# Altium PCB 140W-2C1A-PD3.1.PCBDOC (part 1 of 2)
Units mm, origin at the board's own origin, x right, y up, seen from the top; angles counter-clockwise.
Board outline 57.13 x 21.16 mm, 6 copper layers (Top Layer, G02, P03, Mid-Layer 6, Mid-Layer 20, Bottom Layer), stack 1.489 mm thick; 81 components, 79 nets, 331 pads, 164 vias.
Unrouted connection lines stored in the file: 14.
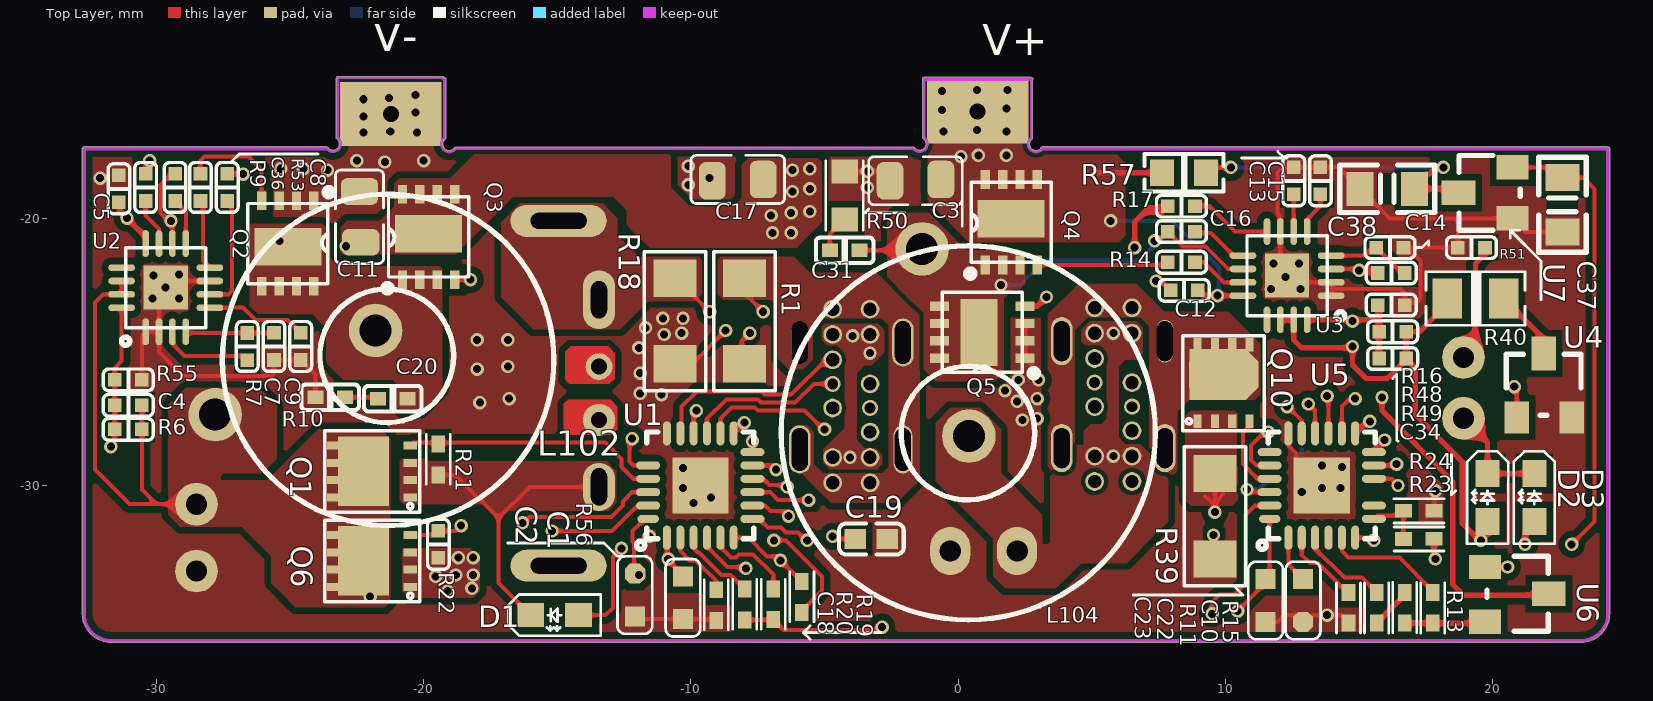
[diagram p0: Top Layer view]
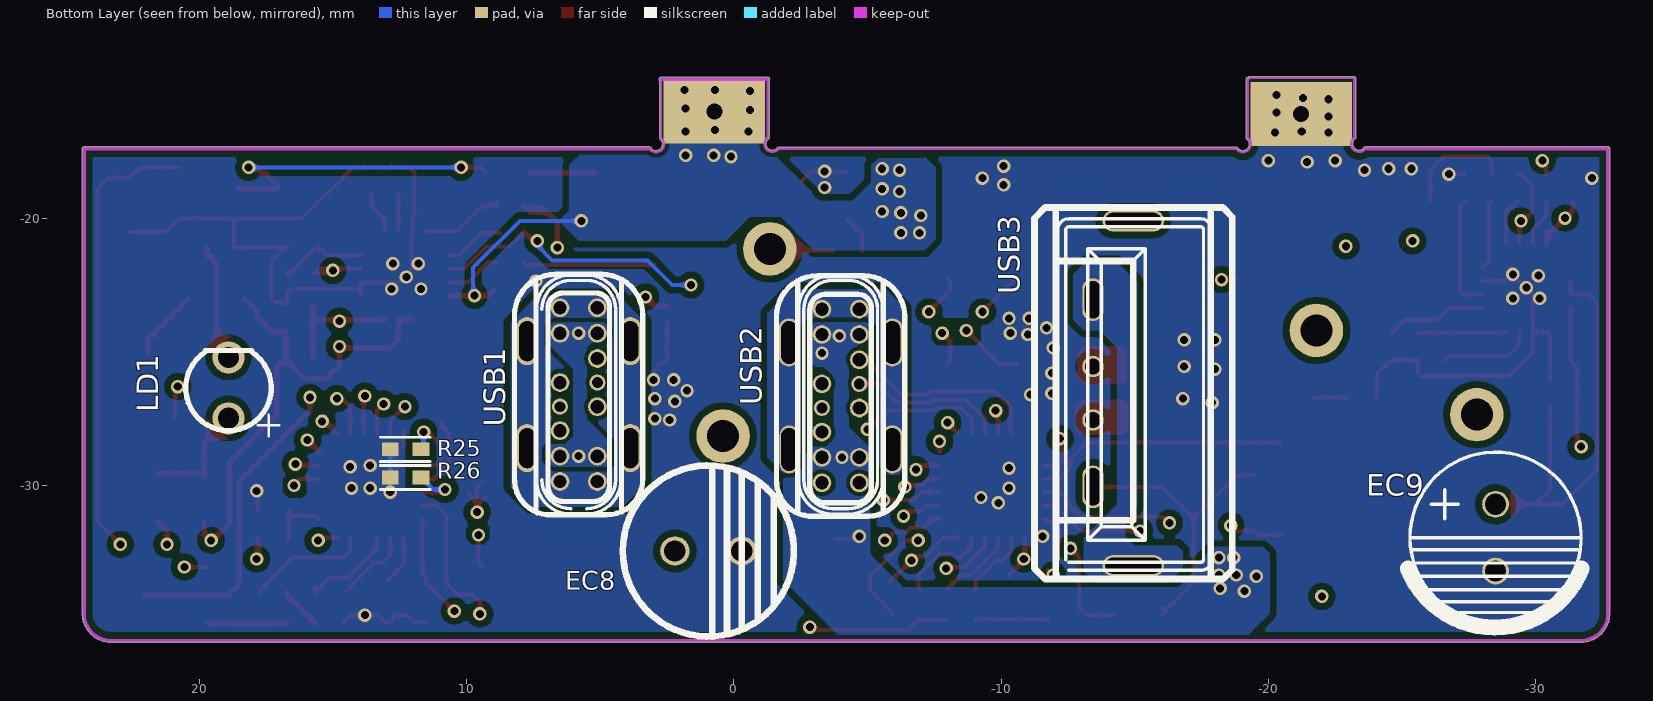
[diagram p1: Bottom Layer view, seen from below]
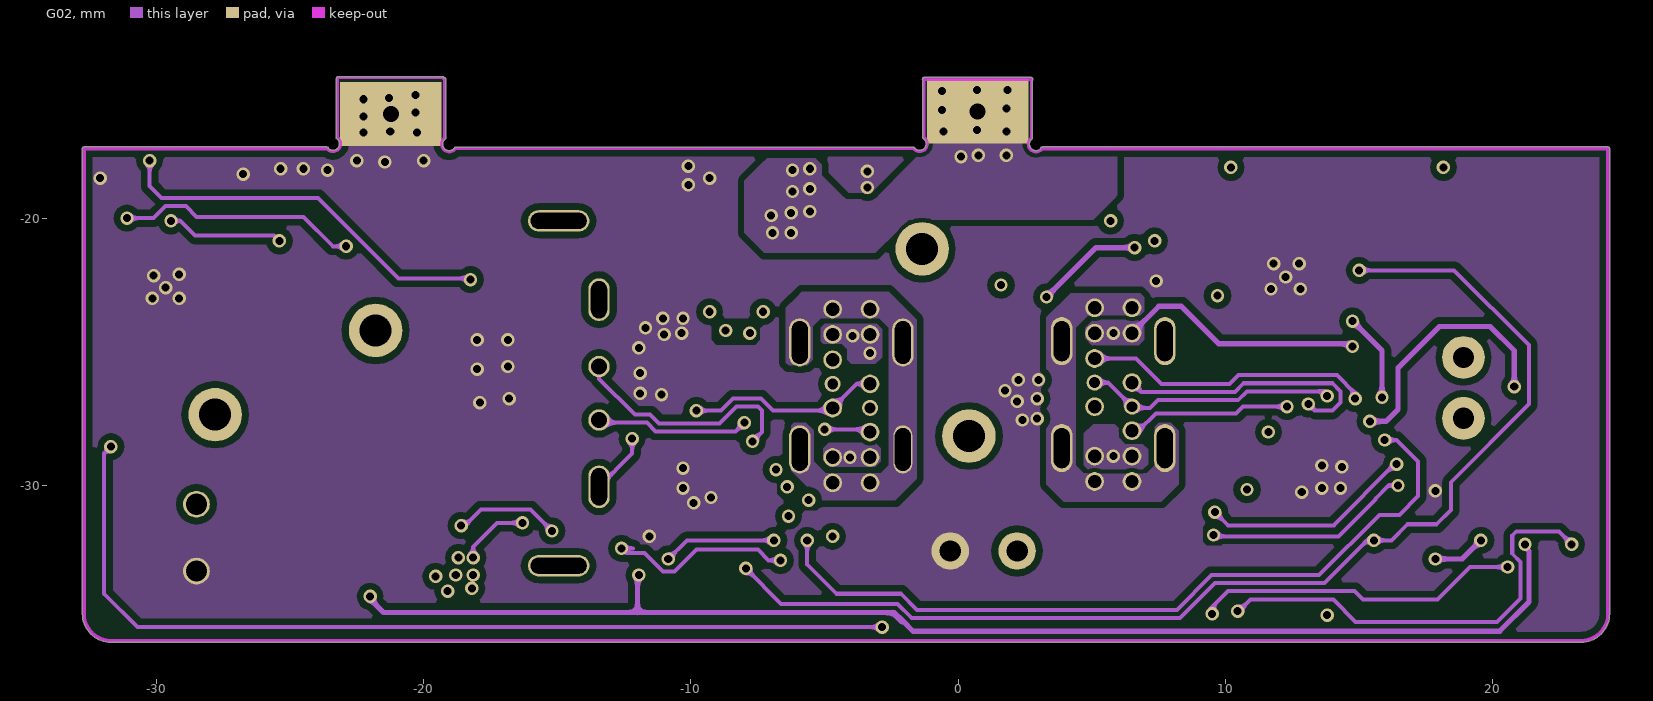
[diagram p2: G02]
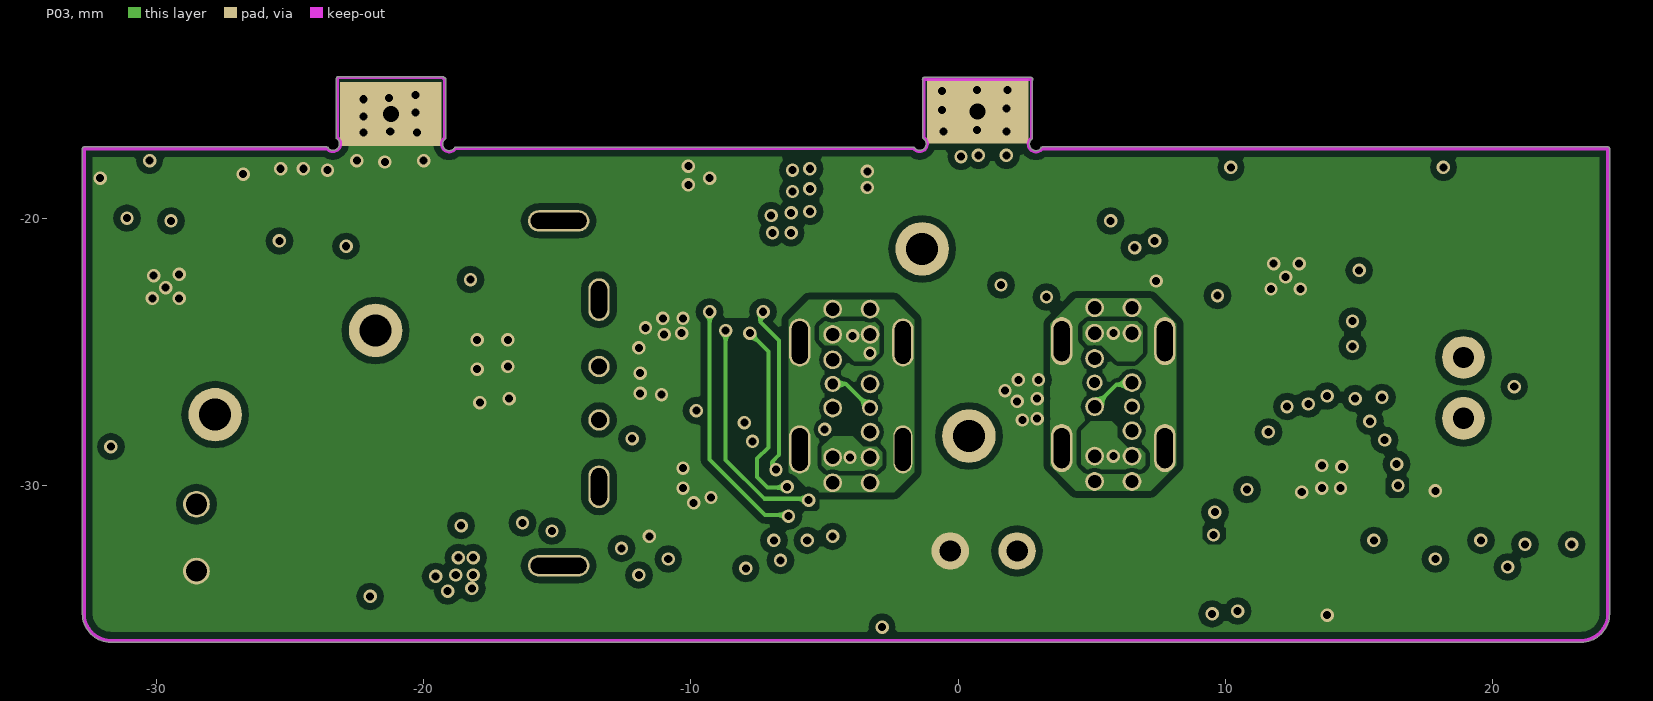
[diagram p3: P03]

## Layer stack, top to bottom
Top Solder: solder mask 0.0102, Solder Resist, Dk 3.5
Top Layer: signal copper 0.0356
Dielectric1: core 0.254, FR-4, Dk 4.2
G02: signal copper 0.036
Dielectric2: prepreg 0.127, Dk 4.2
P03: signal copper 0.036
Dielectric3: core 0.254, Dk 4.2
Mid-Layer 6: signal copper 0.0356
Dielectric4: dielectric 0.32, FR-4, Dk 4.8
Mid-Layer 20: signal copper 0.0356
Dielectric5: dielectric 0.32, FR-4, Dk 4.8
Bottom Layer: signal copper 0.0356
Bottom Solder: solder mask 0.0102, Solder Resist, Dk 3.5

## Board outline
-32.764,-34.8 cw(c-32.7,-34.8) -32.764,-34.799 -32.764,-17.4 cw(c-32.7,-17.4) -32.7,-17.336 -23.625,-17.336 cw(c-23.625,-17.4) -23.561,-17.396 ccw(c-23.393,-17.22) -23.15,-17.22 ccw(c-23.393,-17.22) -23.253,-17.021 cw(c-23.224,-16.98) -23.275,-16.98 -23.275,-14.8 cw(c-23.224,-14.8) -23.25,-14.757 cw(c-23.2,-14.75) -23.2,-14.7 -19.3,-14.7 cw(c-19.3,-14.75) -19.25,-14.75 cw(c-19.3,-14.75) -19.25,-14.756 cw(c-19.225,-14.8) -19.175,-14.8 -19.175,-17 ccw(c-19.225,-17) -19.175,-16.999 -19.175,-17 cw(c-19.225,-17) -19.194,-17.04 ccw(c-19.045,-17.232) -18.846,-17.372 cw(c-18.805,-17.401) -18.805,-17.35 -1.683,-17.35 cw(c-1.675,-17.4) -1.635,-17.369 ccw(c-1.443,-17.22) -1.2,-17.22 ccw(c-1.443,-17.22) -1.303,-17.021 cw(c-1.274,-16.98) -1.325,-16.98 -1.325,-14.839 cw(c-1.274,-14.8) -1.274,-14.736 2.725,-14.736 cw(c2.725,-14.8) 2.789,-14.8 cw(c2.725,-14.8) 2.775,-14.839 2.775,-17 cw(c2.725,-17) 2.756,-17.04 ccw(c2.905,-17.232) 3.081,-17.399 cw(c3.145,-17.4) 3.145,-17.336 24.3,-17.336 cw(c24.3,-17.4) 24.364,-17.4 24.364,-34.8 cw(c24.3,-34.8) 24.364,-34.801 ccw(c23.3,-34.8) 24.364,-34.8 24.364,-34.801 cw(c23.3,-34.8) 23.301,-35.864 cw(c23.3,-35.8) 23.3,-35.864 -31.7,-35.864 cw(c-31.7,-34.8)

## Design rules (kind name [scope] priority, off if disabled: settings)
Clearance Clearance_1 [InNet('NewNet3')] p1: gap=0.254 ignorepadtopadclearanceinfootprint=FALSE except(0: Arc-Hole Track-Hole SMDPad-Hole THPad-Hole Via-Hole Fill-Hole Poly-Hole Region-Hole Text-Hole)
Clearance [All] p2: gap=0.15 ignorepadtopadclearanceinfootprint=FALSE except(0: Arc-Hole Track-Hole SMDPad-Hole THPad-Hole Via-Hole Fill-Hole Poly-Hole Region-Hole Text-Hole)
ComponentClearance [All] p1: gap=0 collisioncheckmode=3 verticalgap=0 showdistances=FALSE
FabricationTestpoint [(IsPad And (OnTopLayer Or OnBottomLayer))] p1: side=3 testpointundercomponent=TRUE minsize=1.016 maxsize=2.54 preferedsize=1.524 minholesize=0 maxholesize=1.016 preferedholesize=0.813 testpointgrid=0.025 allowsidetop=TRUE allowsidebottom=TRUE usegrid=TRUE gridtolerance=0
PolygonConnect [All] p1: connectstyle=Direct reliefconductorwidth=0.254 reliefentries=4 polygonreliefangle="90 Angle" airgapwidth=0.254
RoutingVias [All] p1: holewidth=0.3 width=0.5 viastyle="Through Hole" minholewidth=0.3 minwidth=0.5 maxholewidth=10 maxwidth=10
SilkToSolderMaskClearance SilkscreenOverComponentPads [IsPad] p1: minsilkscreentomaskgap=0.254 clearancetoexposedcopper=TRUE
SolderMaskExpansion [All] p1: expansion=0.102 istentingtop=FALSE
Width [All] p1: maxlimit=10 minlimit=0.15 preferedwidth=0.2
27 further rules are at their usual default settings.

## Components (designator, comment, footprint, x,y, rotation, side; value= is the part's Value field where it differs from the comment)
C1 "2.2uF/25V" 0603C#1 -10.3,-34.2 r270 bottom
C2 "1uF/25V" 0603C#2 -12.1,-34.1 r270 bottom
C3 "25V/10uF" 0805C(W) -1.45,-18.6 r0 top (schematic designator C51)
C4 "50V/220pF" 0402 -31.05,-27 r270 top (schematic designator C39)
C5 "0.1uF" 0402 -31.4,-18.9 r180 top (schematic designator C39)
C7 "2.2uF/10V" 0402 -25.6,-24.8 r0 top (schematic designator C39)
C8 "2.2uF" 0402 -27.35,-18.85 r180 top (schematic designator C49)
C9 "1nF" 0402 -24.6,-24.8 r180 top (schematic designator C35)
C10 "3.3nF" 0402A 15.65,-33.95 r270 top
C11 "25V/10uF" 0805C(W) -22.4,-20.1 r270 top (schematic designator C51)
C12 "0.1uF" 0402 8.45,-22.7 r270 top (schematic designator C39)
C13 "2.2uF/10V" 0402 12.55,-18.6 r180 top (schematic designator C49)
C14 "2.2uF/10V" 0402 16.15,-21.1 r90 top (schematic designator C39)
C15 "1nF" 0402 13.55,-18.6 r0 top (schematic designator C35)
C16 "2.2uF" 0402 8.35,-20.5 r90 top (schematic designator C43)
C17 "10UF/50V  0805" 0805C(W) -8.4,-18.55 r180 top (schematic designator C51)
C18 "15nF" 0402A -7.985,-35.079 r90 top
C19 "1uF/25V" 0603CA -3.25,-32 r180 top
C20 "1nF/50V" CAP-0402 -21.15,-26.75 r180 top (schematic designator C6)
C22 "2.2uF/25V" 0603C#2 12.9,-34.3 r90 bottom
C23 "1uF/25V" 0603C#1 11.5,-34.3 r90 bottom
C31 "1nF/50V" CAP-0402 -4.25,-21.2 r180 top (schematic designator C6)
C34 "50V/220pF" 0402 16.25,-25.25 r90 top (schematic designator C39)
C36 "100nF" 0402 -29.3,-18.85 r0 top (schematic designator C43)
C37 "10uF/25V" CC0805 22.6,-19.5 r90 top
C38 "10UF/35V" CC0805 16.05,-18.9 r180 top
D1 "IN4148" 0603D -15.1,-34.85 r180 bottom
D2 "IN4148  SOD323" 0603D 19.8,-30.45 r90 bottom
D3 "IN4148  SOD323" 0603D 21.55,-30.45 r90 bottom
EC8 "100uF" CE-D6.3-P2.5-PCB -0.3,-32.45 r90 bottom
EC9 "100uF" CE6.3/2.5HA -28.5,-31.95 r180 bottom
L102 "10uH" L13.5*5#1 -21.8,-23.85 r90 top locked
L104 "10uH" L13.5*5#2 0.3,-27.95 r270 top locked
LD1 "Comment" "LED-D3 P2.28" 18.9,-26.35 r270 bottom
Q1 "MOSFET N" DPAK/WAVEAAA#1 -20.5,-28.5 r270 top
Q2 "NMOS" DFN3*3-EPAD -23.6,-19.45 r270 top (schematic designator Q9)
Q3 "NMOS" DFN3*3-EPAD -21.3,-22.2 r90 top (schematic designator Q7)
Q4 "NMOS" DFN3*3-EPAD 0.5,-21.65 r90 top (schematic designator Q7)
Q5 "NMOS" DFN3*3-EPAD 2.4,-25.75 r180 top (schematic designator Q9)
Q6 "MOSFET N" DPAK/WAVEAAA#1 -20.5,-31.85 r270 top
Q10 "MOSFET N" DPAK/WAVEAAA#2 10.9,-27.6 r180 top
R1 "5mR" R1206/WAVE -8,-23.85 r90 top
R6 "100K" 0402 -31.05,-27.9 r90 top (schematic designator R15)
R7 "51K" 0402 -26.6,-24.8 r0 top (schematic designator R15)
R9 "10R" 0402 -30.4,-18.85 r0 top (schematic designator R15)
R10 "2R" CAP-0402 -23.5,-26.7 r180 top (schematic designator R16)
R11 "1K" 0402A 14.6,-33.95 r270 top
R13 "1K   0402" 0402A 17.75,-33.95 r270 top
R14 "10R" 0402 8.35,-21.65 r90 top (schematic designator R15)
R15 "200K" 0402A 16.7,-35.2 r90 top
R16 "51K" 0402 16.2,-22.05 r90 top (schematic designator R15)
R17 "2R" 0402 8.35,-19.55 r270 top (schematic designator R15)
R18 "5mR" R1206/WAVE -10.6,-23.85 r270 top
R19 "100K" 0402A -5.85,-34.8 r90 top
R20 "1K" 0402A -6.919,-35.072 r90 top
R21 "100K" 0402A -19.45,-29.65 r90 top
R22 "100K" 0402 -19.45,-32.2 r0 top (schematic designator R15)
R23 "90K" 0402A 16.6,-32 r0 top
R24 "10K" 0402A 16.6,-30.95 r0 top
R25 "100K" 0402A 11.65,-28.65 r0 bottom
R26 "100K" 0402A 11.65,-29.7 r0 bottom
R39 "5mR" R1206/WAVE 9.6,-31.15 r90 top
R40 "510R" RES-0805A 19.35,-23 r180 top
R48 "16k" 0402 16.2,-23.25 r90 top (schematic designator C38)
R49 "80K" 0402 16.25,-24.25 r90 top (schematic designator R15)
R50 "2R" 0603 -4.25,-19.95 r90 top (schematic designator R16)
R51 "100K  0402" 0402 19.2,-21.1 r90 top (schematic designator R15)
R53 "2R" 0402 -28.35,-18.85 r0 top (schematic designator R15)
R55 "20k" 0402 -31.05,-26.05 r270 top (schematic designator C38)
R56 "1K" 0402A -9.05,-35.1 r90 top
R57 "Comment" RES-0603A 8.45,-18.3 r180 top
U1 "QFN24_0.5" QFN24_0.5#1 -9.65,-30 r90 bottom
U2 "IP6550" QFN16 -29.65,-22.6 r90 top (schematic designator U1)
U3 "IP6550" QFN16 12.3,-22.15 r180 top (schematic designator U1)
U4 "2N7002" SOT23#1 21.9,-26.1 r0 top
U5 "IP2726" QFN24_0.5#2 13.6,-30 r90 bottom
U6 "2N7002" SOT23#1 21.05,-34.05 r270 top
U7 "U103" SOT23#2 19.75,-19.05 r90 top
USB1 "TYPE-C  立式16PIN" L-4P/-P10.0X11.0-W12.0L25.0BAAAABAAA#1 5.8,-26.6 r270 bottom locked
USB2 "TYPE-C  立式16PIN" L-4P/-P10.0X11.0-W12.0L25.0BAAAABAAA#2 -4,-26.65 r270 bottom locked
USB3 "USB_A/6pin" L-4P/-P10.0X11.0-W12.0L25.0BAAAABAB -14.95,-26.55 r180 bottom locked

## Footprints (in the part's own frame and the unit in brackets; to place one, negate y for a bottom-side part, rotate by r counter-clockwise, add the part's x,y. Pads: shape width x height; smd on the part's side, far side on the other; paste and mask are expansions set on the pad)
0402 [mil]
  rect 20x20 smd: 1(0,-19.94) 2(0,19.96)
  silkscreen extent -16,-37 16,37
0402A [mil]
  rect 25x20 smd: 1(1.98,-0.01) 2(47.24,0)
  silkscreen extent -12,-18 62,18
0603 [mm]
  rect 0.9x1 smd: 1(-0.1,0) 2(1.699,0)
  silkscreen extent -0.5,-0.7 2.1,0.7
0603C#1 [mm]
  rect 0.75x0.75 smd far side: 1(-0.8,0) 2(0.8,0)
0603C#2 [mm]
  oct 0.75x0.75 smd far side: 1(-0.8,0)
  rect 0.75x0.75 smd far side: 2(0.8,0)
0603CA [mm]
  rect 0.8x0.75 smd: 1(-0.6,0) 2(0.6,0)
  silkscreen extent -1.21,-0.58 1.21,0.58
0603D [mm]
  rect 1x0.9 smd far side: A(0.895,0) K(-0.895,0)
0805C(W) [mm]
  rrect50% 1x1.4 smd: 1(-1.1,0) 2(0.8,0.05)
  silkscreen extent -1.9,-0.9 1.6,0.9
CAP-0402 [mm]
  rect 0.6x0.5 smd: 1(-0.55,0) 2(0.55,0)
  silkscreen extent -1.08,-0.48 1.08,0.48
CC0805 [mil]
  rect 40x50 smd: 1(-40,0) 2(40,0)
  Top Layer pour cut-out: -15.75,23.62 15.75,23.62 15.75,-23.62 -15.75,-23.62
  silkscreen extent -70,-35 70,35
CE6.3/2.5HA [mm]
  round 1 / inner round 1 / far side round 1.6 hole 0.8: 1(0,1.25) 2(0,-1.25)
  silkscreen extent -3.28,-3.36 3.22,3.2
CE-D6.3-P2.5-PCB [mm]
  round 1.1 / inner round 1.4 / far side oval 1.8x1.5 hole 0.8: 1(0,2.5) 2(0,0)
  silkscreen extent -3.2,-1.95 3.2,4.45
DFN3*3-EPAD [mm]
  rect 0.7x0.35 smd: 1(-0.1,-0.509) 2(-0.1,-1.159) 3(-0.1,-1.809) 4(-0.1,-2.459) 5(3.1,-2.459) 6(3.1,-1.809) 7(3.1,-1.159) 8(3.1,-0.509)
  rect 1.4x2.5 smd: 9(1.625,-1.475)
  silkscreen extent -0.54,-2.98 3,0.17
DPAK/WAVEAAA#1 [mm]
  rect 0.3x0.5 smd: 1(0,-2.86) 4(0.65,-2.86) 5(1.3,-2.86) 6(1.95,-2.86) 7(0.65,0) 8(0,0) 9(1.3,0) 10(1.95,0)
  rect 2.6x1.9 smd: 2(0.97,-1.75)
  rect 1.1x1.9 smd: 3(1.7,-1.75)
  silkscreen extent -0.55,-3.2 2.5,0.35
DPAK/WAVEAAA#2 [mm]
  rect 0.3x0.5 smd: 1(0,-2.86) 4(0.65,-2.86) 5(1.3,-2.86) 6(1.95,-2.86) 7(0.65,0) 8(0,0) 9(1.3,0) 10(1.95,0)
  oct 2.6x1.9 smd: 2(0.97,-1.75)
  rect 1.1x1.9 smd: 3(1.7,-1.75)
  silkscreen extent -0.55,-3.2 2.5,0.35
L13.5*5#1 [mm]
  round 2 hole 1.2: 1(-3.5,6) 2(-0.35,0)
  silkscreen extent -7.65,-6.67 4.75,5.73
L13.5*5#2 [mm]
  round 2 hole 1.2: 1(0.2,0.1) 2(-6.8,-1.65)
  silkscreen extent -6.92,-6.93 7.08,7.07
L-4P/-P10.0X11.0-W12.0L25.0BAAAABAAA#1 [mm]
  oval 1.8x0.8 hole 0.6 slot 1.5 at 0 deg: 1(-2,1.93) 3(2,1.93) 4(2,-1.93)
  oval 1.8x0.8 / inner oval 1.8x0.8 / far side oval 1.6x0.6 hole 0.6 slot 1.5 at 0 deg: 2(-2,-1.93)
  round 0.7 hole 0.5: 5(-3.25,-0.7) 6(-2.3,-0.7) 7(-0.45,-0.7) 9(1.35,-0.7) 10(2.3,-0.7) 11(3.25,-0.7) 12(-3.25,0.7) 13(-2.3,0.7) 14(-1.35,0.7) 16(0.45,0.7) 17(2.3,0.7) 18(3.25,0.7)
  round 0.6 hole 0.4: 8(0.45,-0.7) 15(-0.45,0.7)
  silkscreen extent -4.5,-2.4 4.5,2.4
L-4P/-P10.0X11.0-W12.0L25.0BAAAABAAA#2 [mm]
  oval 1.8x0.8 / inner oval 1.8x0.8 / far side oval 1.6x0.6 hole 0.6 slot 1.6 at 0 deg: 1(-2,1.93)
  oval 1.8x0.8 hole 0.6 slot 1.6 at 0 deg: 2(-2,-1.93) 3(2,1.93)
  oval 1.8x0.7 hole 0.6 slot 1.6 at 0 deg: 4(2,-1.93)
  round 0.7 hole 0.5: 5(-3.25,-0.7) 6(-2.3,-0.7) 7(-0.45,-0.7) 9(1.35,-0.7) 10(2.3,-0.7) 11(3.25,-0.7) 12(-3.25,0.7) 13(-2.3,0.7) 14(-1.35,0.7) 16(0.45,0.7) 17(2.3,0.7) 18(3.25,0.7)
  round 0.6 hole 0.4: 8(0.45,-0.7) 15(-0.45,0.7)
  silkscreen extent -4.5,-2.4 4.5,2.4
L-4P/-P10.0X11.0-W12.0L25.0BAAAABAB [mm]
  oval 2.3x0.8 / inner oval 2.3x0.8 / far side oval 3.6x1.2 hole 0.6 slot 2.1 at 0 deg: 1(0,6.45) 2(0,-6.45)
  round 0.8 / inner round 0.8 / far side round 1 hole 0.6: 3(-1.51,1)
  oval 0.8x1.6 / inner oval 0.8x1.6 / far side oval 1.2x2.2 hole 0.6 slot 1.4 at 90 deg: 4(-1.51,3.5)
  round 0.8 / inner round 0.8 / far side round 1.2 hole 0.6: 5(-1.51,-1)
  oval 0.8x1.6 / inner oval 0.8x1.6 / far side oval 1.2x1.8 hole 0.6 slot 1.4 at 90 deg: 6(-1.51,-3.5)
  silkscreen extent -3.7,-6.95 3.7,6.95
"LED-D3 P2.28" [mm]
  round 1.2 / inner round 1.6 / far side round 1.6 hole 0.8: 1(1.14,0) 2(-1.14,0)
  silkscreen extent -1.4,-1.6 1.8,1.9
QFN16 [mm]
  oval 1x0.25 smd: "1 DN"(-1.65,0.75) "2 DP"(-1.65,0.25) "3 EN"(-1.65,-0.25) "4 VCC"(-1.65,-0.75) "9 BST"(1.65,-0.75) "10 LX"(1.65,-0.25) "11 HG"(1.65,0.25) "12 VIN"(1.65,0.75)
  oval 0.25x1 smd: "5 COMP"(-0.75,-1.65) "6 HVCC"(-0.25,-1.65) "7 PGND"(0.25,-1.65) "8 LG"(0.75,-1.65) "13 VOS1"(0.75,1.65) "14 VOS2"(0.25,1.65) "15 VUOT"(-0.25,1.65) "16 FB"(-0.75,1.65)
  rect 1.65x1.65 smd: 17(0,0)
  silkscreen extent -2.15,-1.5 1.5,1.65
QFN24_0.5#1 [mm]
  oval 0.9x0.3 smd far side: 1(-1.95,-1.25) 2(-1.95,-0.75) 3(-1.95,-0.25) 4(-1.95,0.25) 5(-1.95,0.75) 6(-1.95,1.25) 13(1.95,1.25) 14(1.95,0.75) 15(1.95,0.25) 16(1.95,-0.25) 17(1.95,-0.75) 18(1.95,-1.25)
  oval 0.3x0.9 smd far side: 7(-1.25,1.95) 8(-0.75,1.95) 9(-0.25,1.95) 10(0.25,1.95) 11(0.75,1.95) 12(1.25,1.95) 20(0.75,-1.95) 21(0.25,-1.95) 22(-0.25,-1.95) 23(-0.75,-1.95)
  oval 0.3x0.9 on Top Overlay: 19(1.25,-1.95)
  oval 0.3x0.8 smd far side: 24(-1.25,-1.95)
  rect 2.1x2.1 smd far side: 25(0,0)
QFN24_0.5#2 [mm]
  oval 0.9x0.3 smd far side: 1(-1.95,-1.25) 2(-1.95,-0.75) 3(-1.95,-0.25) 4(-1.95,0.25) 5(-1.95,0.75) 6(-1.95,1.25) 13(1.95,1.25) 14(1.95,0.75) 15(1.95,0.25) 16(1.95,-0.25) 17(1.95,-0.75) 18(1.95,-1.25)
  oval 0.3x0.9 smd far side: 7(-1.25,1.95) 8(-0.75,1.95) 10(0.25,1.95) 11(0.75,1.95) 12(1.25,1.95) 19(1.25,-1.95) 20(0.75,-1.95) 21(0.25,-1.95) 22(-0.25,-1.95) 23(-0.75,-1.95)
  oval 0.3x0.9 on Top Overlay: 9(-0.25,1.95)
  oval 0.3x0.8 smd far side: 24(-1.25,-1.95)
  rect 2.1x2.1 smd far side: 25(0,0)
R1206/WAVE [mm]
  rect 1.4x1.6 smd: 1(-1.6,0) 2(1.6,0)
  silkscreen extent -2.6,-1.15 2.6,1.15
RES-0603A [mm]
  rect 0.9x1 smd: 1(-0.825,0) 2(0.825,0)
  silkscreen extent -1.48,-0.7 1.48,0.7
RES-0805A [mm]
  rect 1.1x1.5 smd: 1(-1.05,0) 2(1.05,0)
  silkscreen extent -1.85,-1 1.85,1
SOT23#1 [mm]
  rect 0.914x1.2 smd: 1(-1,-1.35) 2(1.05,-1.35)
  rect 0.914x1.27 smd: 3(0,1.041)
  silkscreen extent -1.4,-1.27 1.4,1.02
SOT23#2 [mm]
  rect 0.914x1.2 smd: 1(-0.952,-0.991) 2(0.953,-0.991)
  rect 0.914x1.27 smd: 3(0,1.041)
  silkscreen extent -1.4,-1.27 1.4,1.02

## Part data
C3 C4 C5 C7 C11 C12 C14 C17 C34 R48 R55: library part CAP0805, "Capacitor"
C8 C9 C13 C15 C16 C36: library part CAP0603, "Capacitor"
C20 C31: library part C
Q2 Q3 Q4 Q5: library part DFN3333
R6 R7 R9 R14 R16 R17 R22 R49 R51 R53: library part RES, "Resistor"
R10 R50: library part R
U2 U3: library part GC1022_QFN16

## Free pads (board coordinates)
  rect 3.8x2.4 hole 0.6: SGND(-21.225,-16.1) VIN(0.725,-16)

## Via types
v1: diameter 0.5, hole 0.3, Top Layer to Bottom Layer, 164 vias

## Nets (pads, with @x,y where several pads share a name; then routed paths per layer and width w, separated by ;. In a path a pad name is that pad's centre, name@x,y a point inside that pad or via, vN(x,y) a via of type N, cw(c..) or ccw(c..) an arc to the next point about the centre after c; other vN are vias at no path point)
001: R40.1 U4.3 | length 2.7
  Top Layer w0.2: R40.1@20.4,-23 21.9,-24.5 U4.3@21.9,-25.059
002: U4.1 U5.13 | length 11.2
  Top Layer w0.15: v1(20.8,-26.3) 20.9,-26.4 U4.1@20.9,-27.45
  Top Layer w0.2: U5.13@14.85,-28.05 15.3,-27.6 v1(15.4,-27.6)
  G02 w0.2: v1(15.4,-27.6) 16,-27.6 16.45,-27.15 16.45,-25.6 18,-24.05 19.9,-24.05 20.8,-24.95 v1@20.8,-26.1
003: R25.1 U5.20 | length 2.9
  Top Layer w0.15: v1(11.6,-28) 11.45,-28 10.95,-28.5 10.95,-29.05 11.15,-29.25 U5.20@11.65,-29.25
  Bottom Layer w0.15: v1(11.6,-28) 11.6,-28.549 R25.1@11.7,-28.65
004: R26.1 U5.22 | length 2
  Top Layer w0.15: v1(10.8,-30.15) 10.9,-30.25 U5.22@11.65,-30.25
  Bottom Layer w0.15: v1(10.8,-30.15) 11.25,-30.15 R26.1@11.7,-29.7
005: U5.23 U6.1 | length 18.6
  Top Layer w0.15: v1(9.5,-34.8) 9.5,-34.35 9.771,-34.079 10.336,-34.079 10.75,-33.665 10.75,-31.1 11.1,-30.75 U5.23@11.65,-30.75 ; U6.1@19.7,-33.05 v1(20.55,-33.05)
  G02 w0.15: v1(9.5,-34.8) 9.5,-34.55 10.1,-33.95 14.824,-33.95 15.145,-34.271 17.929,-34.271 19.15,-33.05 v1(20.55,-33.05)
006: C38.1 R57.1 U7.3 | length 11.9
  Top Layer w0.15: R57.1@9.275,-18.3 9.475,-18.1 v1(10.2,-18.1)
  Top Layer w0.2: v1(18.15,-18.1) 18.083,-18.167 17.799,-18.167 17.626,-18.34 17.499,-18.34 17.066,-18.773 C38.1@17.066,-18.9 U7.3@18.559,-18.9
  Bottom Layer w0.15: v1(10.2,-18.1) v1(18.15,-18.1)
007: C23.2 C37.2 U5.24 U7.2 | length 37.4
  Top Layer w0.15: v1(10.45,-34.7) 11.5,-33.65 C23.2@11.5,-33.5 11.65,-33.35 U5.24@11.65,-31.25 ; U7.2@20.741,-18.097 22.214,-18.097 C37.2@22.6,-18.484 23.384,-18.484 23.8,-18.9 23.8,-31.35 v1(22.95,-32.2) v1@22.9,-32.25
  G02 w0.15: v1@10.5,-34.7 10.929,-34.271 14.04,-34.271 14.869,-35.1 20.15,-35.1 21.025,-34.225 21.025,-33.247 21.025,-32.853 20.725,-32.553 20.725,-31.875 20.875,-31.725 22.475,-31.725 v1(22.95,-32.2)
008: 
009: 
010: 
NewNet001: LD1.2 R51.1 | length 7.1
  Top Layer w0.15: LD1.2@19.35,-25.16 19.35,-22.457
  Top Layer w0.2: LD1.2@18.9,-25.21 19.35,-24.76 19.35,-21.7 19.707,-21.343 R51.1@19.707,-21.1
NewNet1: "U3.16 FB" C34.2 R13.2 R15.1 R48.2 R49.2 U6.2 U6.3 | length 23
  Top Layer w0.2: 13.05,-23.8 15.643,-23.8 15.743,-23.7 ; R48.2@15.693,-23.25 15.743,-23.3 15.743,-23.7 ; C34.2@15.743,-25.25 15.743,-23.7 ; v1(15.85,-26.7) 15.85,-27.2 18.5,-29.85 18.5,-33.7 18.9,-34.1 U6.3@22.05,-34.1 ; R15.1@16.7,-35.15 R13.2@17.85,-35.15 ; R13.2@17.75,-35.15 19.65,-35.15 U6.2@19.7,-35.1
  G02 w0.2: v1(14.75,-23.85) 15.85,-24.95 v1(15.85,-26.7)
NewNet002: D2.A D3.A LD1.1 | length 4.3
  Top Layer w0.2: LD1.1@18.9,-27.49 19.8,-28.39 D2.A@19.8,-29.555 ; D2.A@19.8,-29.65 D2.A@19.8,-29.555 ; D3.A@21.55,-29.555 D2.A@19.8,-29.555
NewNet2: R13.1 U5.5 | length 4.6
  Top Layer w0.15: U5.5@14.35,-31.95 14.35,-32.45 14.6,-32.7 16.5,-32.7 17.75,-33.95 R13.1@17.75,-34
NewNet003: C10.2 R15.2 | length 1.6
  Top Layer w0.2: C10.2@15.65,-35.15 16.7,-34.1 R15.2@16.7,-34
NewNet3: "U2.1 DN" "U2.2 DP" "U2.7 PGND" "U3.1 DN" "U3.2 DP" "U3.7 PGND" C1.2 C2.2 C3.1 C5.1 C7.1 C8.1 C9.2 C11.1 C12.1 C13.1 C14.1 C15.2 C17.2 C19.1 C22.1 C23.1 C37.1 C38.2 EC8.2 EC9.2 pad.SGND Q2.1 Q2.2 Q2.3 Q5.1 Q5.2 Q5.3 R1.1 R10.2 R11.2 R18.2 R24.2 R25.2 R26.2 R39.1 R48.1 R50.2 R51.2 R55.2 R56.1 U1.9 U1.10 U1.18 U1.25 U2.17 U3.17 U4.2 U5.10 U5.18 U5.25 U7.1 | length 90.7
  Top Layer w0.127: U5.18@12.35,-27.95 12.35,-28.5 12.65,-28.8 U5.25@12.65,-29.4
  Top Layer w0.15: R55.2@-30.543,-26.05 -30.543,-24.393 -30.4,-24.25 -29.9,-24.25 ; -28,-22.35 -29.4,-22.35 v1(-29.65,-22.6) -29.9,-22.85 -29.9,-24.25 ; C8.1@-27.35,-18.344 -26.756,-18.344 v1(-26.75,-18.35) ; R10.2@-24.05,-26.7 -24.05,-25.856 C9.2@-24.6,-25.307 C7.1@-25.6,-25.306 -25.6,-25.8 -25.7,-25.9 -29,-25.9 -29.9,-25 -29.9,-24.25 ; C2.2@-11.75,-35 -11.617,-35 -11.496,-35 -11.134,-35 -11.024,-35 C1.2@-10.3,-35 -9.576,-35 -9.515,-35 ; R18.2@-10.6,-25.45 -9.95,-25.45 v1(-8.7,-24.2) ; -9.449,-35 -9.099,-35 R56.1@-9.05,-35.05 ; R1.1@-8,-25.45 -8.1,-25.35 -8.1,-24.6 v1(-7.8,-24.3) ; U1.9@-7.7,-30.25 -7.05,-30.25 -6.75,-30.55 v1(-5.6,-30.55) ; U1.10@-7.7,-29.75 -7.294,-29.75 -7.061,-29.983 -6.409,-29.983 -6.4,-29.992 v1(-6.4,-30.05) ; R50.2@-4.25,-18.251 -2.899,-18.251 C3.1@-2.55,-18.6 ; Q5.3@2.5,-23.941 Q5.2@2.5,-24.591 Q5.1@2.5,-25.241 3,-25.741 v1(3,-26.05) ; v1(7.4,-22.35) 7.594,-22.35 C12.1@7.944,-22.7 ; R39.1@9.4,-33.05 9.55,-32.9 v1(9.55,-31.85) ; C23.1@11.5,-35.1 11.95,-35.1 12.2,-34.85 12.65,-34.85 C22.1@12.9,-35.1 13.044,-35.1 13.294,-34.85 v1(13.8,-34.85) ; v1@13.903,-34.859 13.912,-34.85 14.363,-34.85 14.6,-35.087 R11.2@14.6,-35.15 ; 13.95,-22.9 13.95,-22.65 ; U5.10@15.55,-29.75 16.2,-29.75 v1(16.45,-30) ; C14.1@16.656,-21.1 C14.1@16.8,-21.1 ; v1@17.726,-30.224 cw(c17.548,-30.402) v1@17.8,-30.402 ; R24.2@17.8,-30.95 17.8,-30.25 v1@17.9,-30.15 ; C37.1@22.6,-20.516 21.254,-20.516 21.182,-20.444 U7.1@20.741,-20.002 18.694,-20.002 ; 13.95,-22.65 13.95,-22.4 12.55,-22.4 U3.17@12.3,-22.15 12.05,-21.9 12.05,-20.5 12.004,-20.454 12.004,-19.883 11.95,-19.829 11.95,-18.3 12.156,-18.094 C13.1@12.55,-18.094 C15.2@13.55,-18.093 14.227,-18.093 C38.2@15.034,-18.9 15.478,-19.344 16.136,-20.002 18.694,-20.002 ; 13.95,-22.65 16.55,-22.65 16.706,-22.806 R48.1@16.706,-23.25 16.806,-23.15 16.855,-23.15 17.15,-23.15 17.3,-23 17.3,-21.6 C14.1@16.8,-21.1 ; C14.1@16.8,-21.1 R51.2@18.694,-21.1 18.694,-20.002
  G02 w0.15: v1(9.55,-31.85) 9.604,-31.904 14.217,-31.904 15.604,-30.517 15.604,-30.496 16.1,-30 v1(16.45,-30)
  P03 w0.15: v1(-8.7,-24.2) -8.7,-29.05 -7.254,-30.496 -5.704,-30.496 v1@-5.6,-30.6 ; v1(-7.8,-24.3) -7.104,-24.996 -7.104,-28.573 -7.529,-28.998 -7.529,-29.69 -7.14,-30.079 -6.429,-30.079 v1(-6.4,-30.05)
  Bottom Layer w0.15: v1@12.85,-30.35 R26.2@12.85,-29.7 R25.2@12.85,-28.65
  other v1: -11.555,-31.905 -9.9,-30.65 -9.25,-30.45 12.85,-30.25 17.85,-30.2 -10.3,-30.1 13.6,-30.1 14.3,-30.1 -10.3,-29.35 14.35,-29.3 13.6,-29.25 2.4,-27.55 2.95,-27.5 -17.9,-26.9 2.2,-26.85 -16.8,-26.75 2.95,-26.75 -11.1,-26.6 -11.9,-26.55 1.75,-26.45 2.25,-26.05 -11.9,-25.8 -18,-25.65 -16.85,-25.55 -11.95,-24.85 -18,-24.55 -16.85,-24.55 -11,-24.35 -10.35,-24.3 -11.7,-24.1 -11.05,-23.75 -10.3,-23.75 -30.15,-23 -29.15,-23 11.7,-22.65 12.8,-22.65 12.25,-22.2 -30.1,-22.15 -29.15,-22.1 11.8,-21.7 12.75,-21.7 -3.4,-18.85 -10.1,-18.75 -32.1,-18.5 -9.3,-18.5 -3.4,-18.25 -23.6,-18.2 -25.35,-18.15 -24.5,-18.15 -10.1,-18.05 -21.45,-17.9 -22.5,-17.85 -20,-17.85 -22.25,-16.8 -20.25,-16.8 -21.25,-16.75 -22.25,-16.2 -20.3,-16.05 -22.25,-15.55 -21.3,-15.5 -20.3,-15.4
NewNet4: R11.1 U5.2 | length 2.9
  Top Layer w0.15: U5.2@12.85,-31.95 12.85,-32.6 13.15,-32.9 13.45,-32.9 R11.1@14.5,-33.95
NewNet5: C10.1 U5.3 | length 4.3
  Top Layer w0.15: 13.55,-32.6 13.35,-32.4 U5.3@13.35,-31.95 13.35,-32.35 14.45,-33.45 15.1,-33.45 15.55,-33.9 C10.1@15.7,-33.9 ; C10.1@15.65,-34 C10.1@15.65,-33.8
NewNet6: R1.2 U1.11 USB2.1 USB2.2 USB2.3 USB2.4 USB2.5 USB2.11 USB2.12 USB2.18 | length 9
  Top Layer w0.15: R1.2@-8,-22.25 -8.1,-22.35 -8.1,-22.7 v1(-7.3,-23.5) ; U1.11@-7.7,-29.25 -6.95,-29.25 -6.9,-29.3 -6.9,-29.341 -6.837,-29.404 v1(-6.821,-29.404)
  P03 w0.15: v1(-7.3,-23.5) -7.4,-23.6 -7.4,-23.881 -6.7,-24.581 -6.7,-28.85 -6.95,-29.1 -6.95,-29.291 -6.837,-29.404 v1(-6.821,-29.404)
NewNet7: C22.2 U5.1 | length 1.8
  Top Layer w0.15: U5.1@12.35,-31.95 12.35,-32.95 12.6,-33.2 C22.2@12.95,-33.55
NewNet8: "U3.14 VOS2" "U3.15 VUOT" C34.1 D2.K EC8.1 L104.1 R23.2 R40.2 R49.1 USB1.6 USB1.10 USB1.13 USB1.17 | length 30.6
  Top Layer w0.2: 12.05,-23.8 12.55,-23.8 12.55,-24.55 12.85,-24.85 v1@14.75,-24.85 ; v1(14.75,-24.8) 14.75,-25.5 15.25,-26 16.05,-26 16.602,-25.448 16.602,-25.404 C34.1@16.756,-25.25 17.1,-25.594 17.1,-27.35 18.85,-29.1 18.85,-31.4 v1@19.5,-32.05 ; C34.1@16.756,-25.25 R49.1@16.757,-24.25 17.25,-24.25 17.85,-23.65 17.85,-23.45 R40.2@18.3,-23 ; R23.2@17.8,-32 17.8,-32.7 v1(17.85,-32.75) ; v1(19.55,-32.05) 19.8,-31.8 D2.K@19.8,-31.345
  G02 w0.2: USB1.6@6.5,-24.3 7.5,-23.3 8.35,-23.3 9.75,-24.7 v1@14.65,-24.7 ; v1(17.85,-32.75) 18.85,-32.75 v1@19.525,-32.075
  other v1: 5.8,-28.9 5.8,-24.3
NewNet9: Q10.8 U5.21 | length 2.9
  Top Layer w0.15: Q10.8@10.9,-27.6 10.9,-27.793 10.65,-28.043 10.65,-29.2 11.2,-29.75 U5.21@11.65,-29.75
NewNet10: 
NewNet11: U5.17 USB1.9 | length 7.4
  Top Layer w0.15: v1(12.3,-27.05) 12.327,-27.05 12.85,-27.573 U5.17@12.85,-28.05
  G02 w0.15: USB1.9@6.5,-27.95 6.75,-27.95 7.4,-27.3 10.399,-27.3 10.649,-27.05 v1(12.3,-27.05)
NewNet12: U5.16 USB1.7 USB1.16 | length 13
  Top Layer w0.15: v1(13.1,-26.95) 13.35,-27.2 U5.16@13.35,-28.05
  G02 w0.15: USB1.7@6.5,-26.15 6.85,-26.5 10.35,-26.5 10.675,-26.175 13.997,-26.175 14.3,-26.478 14.3,-26.9 14,-27.2 13.35,-27.2 v1(13.1,-26.95)
  P03 w0.15: USB1.16@5.1,-27.05 5.925,-26.225 6.425,-26.225 USB1.7@6.5,-26.15
NewNet13: U5.15 USB1.8 USB1.15 | length 10.8
  Top Layer w0.15: v1@13.75,-26.7 13.85,-26.8 U5.15@13.85,-28.05
  G02 w0.15: USB1.15@5.1,-26.15 5.6,-26.15 USB1.8@6.5,-27.05 6.55,-27.1 7.176,-27.1 7.476,-26.8 10.474,-26.8 10.799,-26.475 13.625,-26.475 v1(13.8,-26.65)
NewNet14: U5.14 USB1.14 | length 12.3
  Top Layer w0.15: U5.14@14.35,-28.05 14.35,-27.05 14.6,-26.8 v1@14.8,-26.8
  G02 w0.15: USB1.14@5.1,-25.25 6.65,-25.25 7.6,-26.2 10.15,-26.2 10.475,-25.875 14.175,-25.875 14.85,-26.55 v1(14.85,-26.75)
NewNet15: Q10.1 Q10.2 Q10.3 Q10.4 Q10.5 Q10.6 Q10.7 Q10.9 Q10.10 R39.2 U5.11 USB1.1 USB1.2 USB1.3 USB1.4 USB1.5 USB1.11 USB1.12 USB1.18 | length 13
  Top Layer w0.15: R39.2@9.4,-29.85 9.6,-30.05 v1(9.6,-31) ; U5.11@15.55,-29.25 v1@16.35,-29.25 ; v1@9.6,-31.004 cw(c10.506,-31.004) 9.911,-30.321 ccw(c10.506,-31.004) v1@9.6,-31.004 ; v1@9.6,-31.004 ccw(c8.944,-31.004) 9.229,-30.413 cw(c8.944,-31.004) v1@9.6,-31.004
  G02 w0.15: v1(9.6,-31) 10.1,-31.5 14.05,-31.5 14.05,-31.479 16.329,-29.2 v1(16.4,-29.2)
NewNet16: "U3.3 EN" R16.2 U1.4 U5.6 | length 48.9
  Top Layer w0.15: U1.4@-9.4,-31.95 -9.4,-32.28 -8.63,-33.05 -8,-33.05 v1(-7.95,-33.1) ; 13.95,-21.9 R16.2@15.544,-21.9 ; U5.6@14.85,-31.95 15.45,-31.95 v1(15.55,-32.05) ; v1@15,-22 15.05,-22.05 R16.2@15.694,-22.05
  G02 w0.15: v1(-7.95,-33.1) -6.625,-34.425 -2.265,-34.425 -1.74,-34.95 8.3,-34.95 9.6,-33.65 13.7,-33.65 15.3,-32.05 v1(15.55,-32.05) 16.2,-32.05 16.8,-31.45 17.9,-31.45 18.429,-30.921 18.429,-29.879 21.35,-26.958 21.35,-24.75 18.55,-21.95 v1(15,-21.95)
NewNet17: 
NewNet18: U1.7 U5.12 | length 32.1
  Top Layer w0.15: U1.7@-7.45,-31.25 -7.125,-31.575 -6.625,-31.575 -6.45,-31.75 -6,-31.75 -5.7,-32.05 v1(-5.65,-32.05)
  Top Layer w0.2: U1.7@-7.7,-31.25 U1.7@-7.45,-31.25 ; U5.12@15.55,-28.75 15.55,-28.7 v1(15.95,-28.3)
  G02 w0.15: v1(-5.65,-32.05) -5.65,-32.95 -4.55,-34.05 -2.15,-34.05 -1.55,-34.65 8.176,-34.65 9.476,-33.35 13.5,-33.35 15.75,-31.1 16.5,-31.1 17.2,-30.4 17.2,-29.1 16.4,-28.3 v1(15.95,-28.3)
NewNet19: "U3.10 LX" C16.2 C31.1 L104.2 Q4.1 Q4.2 Q4.3 Q5.5 Q5.6 Q5.7 Q5.8 Q5.9 | length 12.9
  Top Layer w0.15: C31.1@-3.7,-21.2 -1.4,-21.2 L104.2@-1.35,-21.15 ; v1(7.35,-20.85) 7.494,-20.85 C16.2@7.844,-20.5 8.394,-21.05 9.25,-21.05 10.1,-21.9 10.65,-21.9
  Bottom Layer w0.15: v1(1.6,-22.5) 2.3,-22.5 3.225,-21.575 6.797,-21.575 7.35,-21.022 v1(7.35,-20.85)
NewNet20: Q5.4 R17.1 | length 8.5
  Top Layer w0.2: Q5.4@2.5,-23.291 2.959,-23.291 v1(3.3,-22.95) ; v1@6.6,-21.2 v1(6.6,-21.1) 6.6,-20.15 6.975,-19.775 ; R17.1@7.843,-19.6 7.15,-19.6 6.975,-19.775 ; R17.1@7.843,-19.55 7.618,-19.775 6.975,-19.775
  G02 w0.2: v1(3.3,-22.95) 5.15,-21.1 v1(6.6,-21.1)
NewNet21: "U2.12 VIN" "U3.12 VIN" C3.2 C5.2 C11.2 C12.2 C17.1 pad.VIN Q3.5 Q3.6 Q3.7 Q3.8 Q3.9 Q4.5 Q4.6 Q4.7 Q4.8 Q4.9 R57.2 | length 21.4
  Top Layer w0.2: C5.2@-31.4,-19.407 -31.4,-19.7 -30.4,-20.7 -30.4,-20.95 -30.4,-20.55 ; 5.2,-18.3 R57.2@7.625,-18.3 ; C12.2@8.957,-22.7 9.157,-22.9 10.65,-22.9
  G02 w0.15: v1(-31.1,-20) -30.1,-20 -29.65,-19.55 -28.9,-19.55 -28.5,-19.95 -24.5,-19.95 -23.4,-21.05 v1(-22.9,-21.05)
  Bottom Layer w0.15: v1(5.7,-20.1) 8,-20.1 9.75,-21.85 v1@9.75,-22.9
  other v1: 9.7,-22.9 -6.95,-20.55 -6.25,-20.55 -7,-19.9 -6.25,-19.8 -5.55,-19.75 -6.2,-19 -5.55,-18.9 -6.2,-18.2 -5.55,-18.15 0.1,-17.7 0.75,-17.65 1.8,-17.65 -0.55,-16.75 1.8,-16.75 0.7,-16.7 -0.6,-15.95 1.8,-15.9 -0.6,-15.25 0.7,-15.2 1.85,-15.2
NewNet22: "U3.11 HG" R14.1 | length 2.1
  Top Layer w0.15: R14.1@8.857,-21.65 9.2,-21.65 9.95,-22.4 10.65,-22.4
NewNet23: "U3.9 BST" C16.1 | length 2.3
  Top Layer w0.15: C16.1@8.75,-20.55 9.45,-20.55 10.3,-21.4 10.65,-21.4
NewNet24: "U3.8 LG" R17.2 | length 3.9
  Top Layer w0.15: R17.2@8.856,-19.55 9.4,-19.55 10.35,-20.5 11.55,-20.5 ; R17.2@8.856,-19.429 cw(c8.856,-20.45) 9.578,-19.728
NewNet25: "U3.6 HVCC" C13.2 | length 1.4
  Top Layer w0.15: 12.55,-20.5 C13.2@12.55,-19.106
NewNet26: "U3.5 COMP" C15.1 | length 1.6
  Top Layer w0.15: 13.05,-20.5 13.05,-20.05 13.55,-19.55 C15.1@13.55,-19.106
NewNet27: "U3.4 VCC" C14.2 R16.1 | length 3.9
  Top Layer w0.15: 13.95,-21.4 15.2,-21.4 C14.2@15.55,-21.05 ; C14.2@15.543,-21.2 C14.2@15.643,-21.1 16.643,-22.1 R16.1@16.707,-22.1 ; R16.1@16.463,-21.92 ccw(c16.707,-21.676) 16.707,-22.021 cw(c16.707,-21.676) R16.1@16.463,-21.92
NewNet28: R23.1 R24.1 U5.7 | length 2.3
  Top Layer w0.15: U5.7@15.55,-31.25 15.675,-31.125 16.476,-31.125 R24.1@16.65,-30.95 R23.1@16.65,-32
NewNet29: Q4.4 R14.2 | length 4.9
  Top Layer w0.15: Q4.4@2.959,-21.75 7.744,-21.75 R14.2@7.844,-21.65
NewNet30: U5.19
NewNet31: 
NewNet32: 
NewNet33: Q3.4 R9.2 | length 15.7
  Top Layer w0.15: R9.2@-30.4,-18.344 -30.4,-17.95 v1@-30.2,-17.75 ; Q3.4@-18.841,-22.3 v1(-18.25,-22.3)
  G02 w0.15: v1(-30.25,-17.85) -30.25,-18.8 -29.8,-19.25 -23.95,-19.25 -20.95,-22.25 v1@-18.2,-22.25
NewNet34: "U2.10 LX" C20.1 C36.2 L102.2 Q2.5 Q2.6 Q2.7 Q2.8 Q2.9 Q3.1 Q3.2 Q3.3 | length 7.5
  Top Layer w0.15: -29.4,-20.95 -29.4,-20.25 -29.85,-19.8 -29.85,-18.75 -29.443,-18.343 C36.2@-29.3,-18.343
  G02 w0.15: v1(-29.45,-20.1) -29.1,-20.1 -28.55,-20.65 -25.6,-20.65 v1(-25.4,-20.85)
NewNet35: Q2.4 R53.2 | length 4.2
  Top Layer w0.15: R53.2@-28.35,-18.344 -28.35,-17.85 -28.2,-17.7 -26.55,-17.7 -26.059,-18.191 Q2.4@-26.059,-19.35
NewNet36: "U2.4 VCC" C7.2 R7.2 | length 3.3
  Top Layer w0.15: -28.9,-24.25 -28.857,-24.293 C7.2@-25.6,-24.293
NewNet37: "U2.3 EN" R7.1 | length 3.5
  Top Layer w0.15: -29.4,-24.25 -29.4,-24.7 -28.95,-25.15 -26.757,-25.15 R7.1@-26.6,-25.307
NewNet38: 
NewNet39: "U2.5 COMP" C9.1 | length 3.8
  Top Layer w0.15: -28,-23.35 -26.75,-23.35 -26.3,-23.8 -25.094,-23.8 C9.1@-24.6,-24.294
NewNet40: "U2.6 HVCC" C8.2 | length 4.3
  Top Layer w0.15: -28,-22.85 -27.3,-22.85 -27.171,-22.721 -27.171,-19.536 C8.2@-27.35,-19.357
NewNet41: "U2.16 FB" C4.1 C18.1 R6.2 R20.1 R55.1 | length 45.9
  Top Layer w0.15: v1(-31.7,-28.55) -31.556,-28.406 C4.1@-31.556,-27 R55.1@-31.556,-26.05 -31.556,-25.606 -31.3,-25.35 -31.3,-23.35 ; C18.1@-7.985,-35.029 -6.926,-35.029 R20.1@-6.918,-35.021 -6.539,-35.4 -2.95,-35.4 v1(-2.85,-35.3)
  G02 w0.15: v1(-31.7,-28.55) -31.95,-28.8 -31.95,-34.05 -30.7,-35.3 v1(-2.85,-35.3)
NewNet42: "U2.14 VOS2" "U2.15 VUOT" C2.1 C4.2 D3.K EC9.1 L102.1 Q1.1 Q1.2 Q1.3 Q1.4 Q1.5 Q1.6 Q6.1 Q6.2 Q6.3 Q6.4 Q6.5 Q6.6 R6.1 U1.24 | length 68.5
  Top Layer w0.15: -31.3,-22.35 -31.3,-22.85 -32,-22.85 -32.3,-23.15 -32.3,-29.4 -31,-30.7 -30,-30.7 ; C4.2@-30.543,-27 R6.1@-30.543,-27.9 -30.543,-30.157 -30,-30.7 ; EC9.1@-28.5,-30.7 -30,-30.7 ; C2.1@-11.862,-33.438 ccw(c-12.131,-33.169) C2.1@-11.75,-33.169 ; C2.1@-11.75,-33.4 -12.125,-33.025 -12.125,-32.153 -12.179,-32.099 -12.179,-31.71 -11.719,-31.25 U1.24@-11.6,-31.25
  Top Layer w0.2: v1(21.2,-32.2) 21.2,-31.695 D3.K@21.55,-31.345
  G02 w0.2: v1@-22,-34.2 -22,-34.25 -21.5,-34.75 -12,-34.75 ; v1@-12,-33.4 -12,-34.75 ; -2.1,-35.1 -2.45,-34.75 -2.4,-34.75 ; v1@21.15,-32.25 21.35,-32.45 21.35,-34.36 20.256,-35.454 -1.696,-35.454 -2.075,-35.075 -2.4,-34.75 ; -12,-34.75 -2.4,-34.75
  other v1: -22,-34.15 -11.95,-33.35
NewNet43: "U2.11 HG" R9.1 | length 1.8
  Top Layer w0.15: R9.1@-30.4,-19.357 -30.4,-19.9 -29.9,-20.4 -29.9,-20.95
NewNet44: "U2.9 BST" C36.1 | length 1.8
  Top Layer w0.15: C36.1@-29.3,-19.356 -28.9,-19.756 -28.9,-20.95
NewNet45: "U2.8 LG" R53.1 | length 2.6
  Top Layer w0.15: R53.1@-28.35,-19.357 -28.25,-19.457 -28.25,-21.6 -28,-21.85
NewNet46: D1.A Q1.7 Q1.9 Q1.10 R21.1 U1.20 USB3.6 | length 15.9
  Top Layer w0.15: R21.1@-19.45,-29.6 -18.825,-29.6 -17.2,-31.225 ; D1.A@-15.995,-34.85 -17.2,-33.645 -17.2,-31.225 ; USB3.6@-13.44,-30.05 -16.025,-30.05 -17.2,-31.225 ; v1(-12.2,-28.25) -12.3,-28.35 -12.3,-29.1 -12.15,-29.25 U1.20@-11.6,-29.25 ; D1.A@-16.344,-34.501 ccw(c-16.045,-34.203) -16.045,-34.625 cw(c-16.045,-34.203) D1.A@-16.344,-34.501
  G02 w0.15: USB3.6@-13.44,-30.05 -12.2,-28.81 v1(-12.2,-28.25)
NewNet47: Q1.8 R21.2 U1.21 | length 9.7
  Top Layer w0.15: Q1.8@-20.5,-28.5 -20.4,-28.4 -13.2,-28.4 -12.6,-29 -12.6,-29.3 -12.15,-29.75 U1.21@-11.6,-29.75
NewNet48: C1.1 R19.1 U1.1 | length 10
  Top Layer w0.15: U1.1@-10.9,-31.95 -10.9,-32.75 -10.3,-33.35 C1.1@-10.3,-33.4 ; v1(-6.9,-32.05) -6.45,-32.05 -5.1,-33.4 -5.1,-33.937 -5.671,-34.507 -5.9,-34.736 R19.1@-5.9,-34.8
  G02 w0.15: v1(-10.85,-32.75) -10.15,-32.05 v1(-6.9,-32.05)
NewNet49: R56.2 U1.2 | length 2.6
  Top Layer w0.15: U1.2@-10.4,-31.95 -10.4,-32.45 -10.05,-32.8 -9.832,-32.8 -9.05,-33.582 R56.2@-9.05,-33.9
NewNet50: R20.2 U1.5 | length 3.4
  Top Layer w0.15: U1.5@-8.9,-31.95 -8.9,-32.3 -8.5,-32.7 -8.32,-32.7 -8.195,-32.575 -7.675,-32.575 -6.918,-33.332 R20.2@-6.918,-33.872
NewNet51: C18.2 U1.3 | length 2.9
  Top Layer w0.15: U1.3@-9.9,-31.95 -9.9,-32.35 -9.75,-32.5 -9.708,-32.5 -8.858,-33.35 -8.515,-33.35 C18.2@-7.985,-33.879
NewNet52: C31.2 R50.1 | length 1.4
  Top Layer w0.15: C31.2@-4.8,-21.2 -4.8,-20.6 R50.1@-4.25,-20.05
NewNet53: Q6.8 R22.2 U1.23 | length 10.1
  Top Layer w0.15: Q6.8@-20.5,-31.85 -19.606,-31.85 R22.2@-19.45,-31.694 -18.794,-31.694 v1(-18.6,-31.5) ; v1@-15.25,-31.7 v1(-15.2,-31.7) -12.95,-31.7 -12,-30.75 U1.23@-11.6,-30.75
  G02 w0.15: v1(-18.6,-31.5) -18.45,-31.5 -17.85,-30.9 -16,-30.9 v1(-15.2,-31.7)
NewNet54: C19.2 Q6.7 Q6.9 Q6.10 R22.1 U1.22 USB2.6 USB2.10 USB2.13 USB2.17 | length 8.8
  Top Layer w0.15: v1@-16.35,-31.4 v1(-16.3,-31.4) -16.25,-31.4 -16.025,-31.175 -12.975,-31.175 -12.55,-30.75 -12.55,-30.6 -12.2,-30.25 U1.22@-11.6,-30.25 ; v1(-4.7,-31.9) -4.6,-32 C19.2@-3.85,-32
  G02 w0.15: v1(-18.15,-32.7) -18.15,-32.3 -17.25,-31.4 v1(-16.3,-31.4)
  other v1: -19.1,-33.95 -18.2,-33.85 -19.55,-33.4 -18.8,-33.35 -18.15,-33.35 -18.7,-32.7 -4.05,-28.95 -3.3,-25.05 -3.95,-24.4
NewNet55: U1.17 USB2.14 | length 7.9
  Top Layer w0.15: U1.17@-10.4,-28.05 -10.35,-28 -10.35,-27.6 ; -10.35,-27.2 -10.35,-27.6 ; USB2.14@-4.7,-25.3 -4.95,-25.3 -6.25,-26.6 -7.252,-26.6 -7.373,-26.479 -9.779,-26.479 -10.35,-27.05 -10.35,-27.6
NewNet56: U1.16 USB2.7 USB2.16 | length 8.2
  Top Layer w0.15: U1.16@-9.9,-28.05 v1@-9.9,-27.15
  G02 w0.15: v1(-9.8,-27.2) -8.874,-27.2 -8.424,-26.75 -7.376,-26.75 -6.926,-27.2 -4.8,-27.2 USB2.16@-4.7,-27.1 -3.8,-26.2 USB2.7@-3.3,-26.2
NewNet57: U1.15 USB2.8 USB2.15 | length 7.7
  Top Layer w0.15: U1.15@-9.4,-28.05 -9.4,-27.5 -8.679,-26.779 -7.497,-26.779 -7.376,-26.9 -6.1,-26.9 -5.4,-26.2 USB2.15@-4.7,-26.2
  P03 w0.15: USB2.15@-4.7,-26.2 -4.2,-26.2 USB2.8@-3.3,-27.1
NewNet58: U1.14 USB2.9 | length 6.8
  Top Layer w0.15: U1.14@-8.9,-28.05 -8.9,-27.5 -8.479,-27.079 -7.621,-27.079 -7.5,-27.2 -5.75,-27.2 v1@-4.95,-28
  G02 w0.15: v1(-5,-27.9) -3.4,-27.9 USB2.9@-3.3,-28
NewNet59: U1.13 USB3.5 | length 7
  Top Layer w0.15: U1.13@-8.4,-28.05 v1(-8,-27.65)
  G02 w0.15: USB3.5@-13.44,-27.55 -13.34,-27.65 -11.65,-27.65 -11.325,-27.975 -8.325,-27.975 v1(-8,-27.65) ; USB3.5@-13.21,-27.78 cw(c-12.897,-28.093) -12.897,-27.65 ccw(c-12.897,-28.093) USB3.5@-13.21,-27.78
NewNet60: U1.12 USB3.3 | length 9.3
  Top Layer w0.15: U1.12@-7.7,-28.75 v1(-7.7,-28.35)
  G02 w0.15: USB3.3@-13.44,-25.55 -13.44,-26.01 -12.1,-27.35 -11.526,-27.35 -11.201,-27.675 -8.925,-27.675 -8.3,-27.05 -7.5,-27.05 -7.35,-27.2 -7.35,-28 v1(-7.7,-28.35)
NewNet61: R18.1 U1.8 USB3.1 USB3.2 USB3.4 | length 12.6
  Top Layer w0.15: R18.1@-10.6,-22.25 -10.55,-22.25 v1(-9.3,-23.5) ; U1.8@-7.7,-30.75 -7.226,-30.75 -7.022,-30.954 -6.496,-30.954 -6.35,-31.1 v1(-6.35,-31.15)
  P03 w0.15: v1(-9.3,-23.5) -9.3,-29.021 -7.221,-31.1 v1@-6.45,-31.1
NewNet62: D1.K R19.2 U1.6 | length 14.5
  Top Layer w0.15: D1.K@-14.205,-34.85 -13.2,-34.85 -12.925,-34.575 -12.925,-32.675 v1(-12.6,-32.35) v1@-12.6,-32.3 ; U1.6@-8.4,-31.95 -7.85,-31.95 -7.15,-32.65 -6.8,-32.65 v1(-6.65,-32.8) R19.2@-5.85,-33.6
  G02 w0.15: v1(-12.6,-32.35) -12.421,-32.529 -11.743,-32.529 -11.047,-33.225 -10.625,-33.225 -9.8,-32.4 -7.5,-32.4 -7.1,-32.8 v1(-6.65,-32.8) ; v1@-12.476,-32.474 cw(c-12.178,-32.772) -12.178,-32.35 cw(c-12.178,-31.928) v1@-12.476,-32.226
NewNet63: 
NewNet64: 
NewNet65: 
NewNet66: C20.2 R10.1 | length 1.3
  Top Layer w0.15: R10.1@-22.95,-26.7 -21.75,-26.7 C20.2@-21.7,-26.75
pads on no net: "U2.13 VOS1" "U3.13 VOS1" U1.19 U5.4 U5.8 U5.9

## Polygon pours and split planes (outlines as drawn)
NewNet3 on Top Layer "Top Layer-No Net" (solid, remove dead copper, pour order 1158): -32.764,-34.8 cw(c-32.7,-34.8) -32.764,-34.799 -32.764,-17.4 cw(c-32.7,-17.4) -32.7,-17.336 -23.625,-17.336 cw(c-23.625,-17.4) -23.561,-17.396 ccw(c-23.393,-17.22) -23.15,-17.22 ccw(c-23.393,-17.22) -23.253,-17.021 cw(c-23.224,-16.98) -23.275,-16.98 -23.275,-14.8 cw(c-23.224,-14.8) -23.25,-14.757 cw(c-23.2,-14.75) -23.2,-14.7 -19.3,-14.7 cw(c-19.3,-14.75) -19.25,-14.75 cw(c-19.3,-14.75) -19.25,-14.756 cw(c-19.225,-14.8) -19.175,-14.8 -19.175,-17 ccw(c-19.225,-17) -19.175,-16.999 -19.175,-17 cw(c-19.225,-17) -19.194,-17.04 ccw(c-19.045,-17.232) -18.846,-17.372 cw(c-18.805,-17.401) -18.805,-17.35 -1.683,-17.35 cw(c-1.675,-17.4) -1.635,-17.369 ccw(c-1.443,-17.22) -1.2,-17.22 ccw(c-1.443,-17.22) -1.303,-17.021 cw(c-1.274,-16.98) -1.325,-16.98 -1.325,-14.839 cw(c-1.274,-14.8) -1.274,-14.736 2.725,-14.736 cw(c2.725,-14.8) 2.789,-14.8 cw(c2.725,-14.8) 2.775,-14.839 2.775,-17 cw(c2.725,-17) 2.756,-17.04 ccw(c2.905,-17.232) 3.081,-17.399 cw(c3.145,-17.4) 3.145,-17.336 24.3,-17.336 cw(c24.3,-17.4) 24.364,-17.4 24.364,-34.8 cw(c24.3,-34.8) 24.364,-34.801 ccw(c23.3,-34.8) 24.364,-34.8 24.364,-34.801 cw(c23.3,-34.8) 23.301,-35.864 cw(c23.3,-35.8) 23.3,-35.864 -31.7,-35.864 cw(c-31.7,-34.8)
NewNet8 on Top Layer "NONET_L-01_P-001" (solid, remove dead copper, pour order 1144): 4.775,-23.775 6.575,-23.775 6.9,-24.1 6.9,-25.05 6.65,-25.3 6.25,-25.3 6,-25.55 6,-28.2 6.25,-28.45 6.8,-28.45 6.95,-28.6 6.95,-29.2 6.85,-29.3 4.85,-29.3 4.7,-29.15 4.7,-27.95 4.95,-27.7 5.35,-27.7 5.55,-27.5 5.55,-25 5.3,-24.75 4.75,-24.75 4.6,-24.6 4.6,-24.1 4.85,-23.85
NewNet8 on Top Layer "Top Layer-NewNet4" (solid, remove dead copper, pour order 1117): 2.7,-31.7 3.2,-32.2 3.25,-32.2 3.35,-32.2 3.4,-32.15 3.45,-32.1 3.45,-31.9 3.45,-29.35 4.3,-28.5 6.25,-28.5 6.85,-28.5 7.05,-28.7 7.85,-29.5 7.85,-29.75 7.85,-31.35 7.45,-31.75 6.3,-32.9 4.95,-32.9 4.6,-32.9 4.2,-33.3 3.65,-33.85 1.9,-33.85 1.75,-33.85 1.4,-33.5 1.3,-33.4 1.3,-32.9 1.3,-32.65 2,-31.95
NewNet8 on Top Layer "Top Layer-NewNet4" (solid, remove dead copper, pour order 1126): 0.8,-27.1 1.6,-27.9 1.6,-29.55 3.15,-31.1 3.15,-32.95 1.3,-32.95 1.3,-32 -0.85,-29.85 -0.85,-27.65 -0.3,-27.1
NewNet54 on Top Layer "Top Layer-NewNet4" (solid, remove dead copper, pour order 1131): -5.05,-29.1 -5.05,-28.65 -4.75,-28.35 -4.25,-27.85 -4.25,-27.05 -4.25,-25.05 -4.45,-24.85 -4.55,-24.75 -4.8,-24.75 -4.9,-24.75 -5.1,-24.55 -5.1,-24.05 -5,-23.95 -4.05,-23.95 -3,-23.95 -2.85,-24.1 -2.75,-24.2 -2.75,-24.65 -2.75,-25 -3,-25.25 -3.25,-25.5 -3.5,-25.5 -3.8,-25.8 -3.8,-26.05 -3.8,-28.3 -3.65,-28.45 -3.5,-28.6 -3.25,-28.6 -3.1,-28.6 -2.95,-28.75 -2.85,-28.85 -2.85,-29.15 -2.85,-29.2 -2.95,-29.3 -3.05,-29.4 -3.55,-29.4 -4.8,-29.4 -5.05,-29.15
NewNet6 on Top Layer "Top Layer-NewNet4" (solid, remove dead copper, pour order 1130): -8.9,-21.45 -6.15,-21.45 -5.7,-21.9 -5.55,-22.05 -4,-22.05 -3.05,-22.05 -2,-23.1 -1.45,-23.65 -1.45,-24.6 -1.45,-29.8 -1.85,-30.2 -2.3,-30.65 -4.55,-30.65 -4.75,-30.65 -5.1,-30.3 -6.3,-29.1 -6.3,-28.4 -6.3,-27.95 -6.15,-27.8 -6.1,-27.75 -5.9,-27.75 -5.65,-27.75 -5.6,-27.8 -5.4,-28 -5.4,-28.15 -5.4,-29.2 -5.2,-29.4 -5.05,-29.55 -4.35,-29.55 -2.85,-29.55 -2.7,-29.4 -2.6,-29.3 -2.6,-29.05 -2.6,-24 -2.8,-23.8 -2.85,-23.75 -3.35,-23.75 -5.25,-23.75 -5.4,-23.9 -5.45,-23.95 -5.45,-24.6 -5.45,-25.3 -5.75,-25.6 -5.8,-25.65 -6.15,-25.65 -6.35,-25.65 -6.55,-25.45 -6.75,-25.25 -6.75,-23.9 -6.75,-23.3 -6.9,-23.15 -7,-23.05 -7.2,-23.05 -8.8,-23.05 -9,-22.85 -9,-21.7 -9,-21.55 -8.9,-21.45
NewNet61 on Top Layer "Top Layer-NewNet4" (solid, remove dead copper, pour order 1129): -16.3,-19.45 -13.3,-19.45 -13,-19.75 -12.75,-20 -12.75,-20.25 -12.75,-20.65 -12.4,-21 -11.95,-21.45 -10.75,-21.45 -9.7,-21.45 -9.65,-21.5 -9.6,-21.55 -9.6,-22 -9.6,-22.85 -9.8,-23.05 -9.85,-23.1 -10.95,-23.1 -11.6,-23.1 -12.05,-23.55 -12.65,-24.15 -13.8,-24.15 -15.9,-24.15 -16.65,-23.4 -17.1,-22.95 -17.1,-20.55 -17.1,-20.15 -16.4,-19.45
NewNet42 on Top Layer "Top Layer-NewNet4" (solid, remove dead copper, pour order 1128): -27.35,-26.35 -28.9,-26.35 -29.25,-26.7 -29.55,-27 -29.55,-29.8 -29.55,-31.1 -29.35,-31.3 -29.1,-31.55 -28.6,-31.55 -26.8,-31.55 -26.05,-32.3 -25.7,-32.65 -25.7,-33.2 -25.7,-33.65 -25.35,-34 -24.8,-34.55 -21.7,-34.55 -21.45,-34.55 -21.2,-34.3 -21.25,-34.25 -21.25,-33.45 -21.25,-28.25 -21.4,-28.1 -21.6,-27.9 -21.95,-27.9 -23.95,-27.9 -25.2,-29.15 -25.85,-29.8 -27.4,-29.8 -27.55,-29.8 -27.6,-29.75 -27.6,-29.65 -27.5,-29.55 -27.45,-29.55 -26.85,-29.55 -26.05,-29.55 -25.7,-29.2 -25.5,-29 -25.5,-27.4 -25.5,-27 -26.15,-26.35
NewNet34 on Top Layer "Top Layer-NewNet4" (solid, remove dead copper, pour order 1127): -26.45,-20.2 -23.8,-20.2 -23.7,-20.3 -23.5,-20.5 -23.5,-20.75 -23.5,-21.5 -23.35,-21.65 -23.2,-21.8 -22.4,-21.8 -19.4,-21.8 -19.3,-21.9 -19.3,-26.45 -20.05,-27.2 -20.1,-27.25 -20.5,-27.25 -20.8,-27.25 -21,-27.05 -21,-26.4 -21,-26.2 -21.1,-26.1 -21.15,-26.05 -21.95,-26.05 -23,-26.05 -23.2,-25.85 -23.65,-25.4 -23.65,-24.95 -23.65,-24.1 -23.9,-23.85 -24.15,-23.6 -24.65,-23.6 -26.2,-23.6 -26.45,-23.35 -26.5,-23.3 -26.5,-22.4 -26.5,-20.25 -26.45,-20.2
NewNet19 on Top Layer "Top Layer-NewNet4" (solid, remove dead copper, pour order 1125): 2.5,-22.15 2.5,-21.3 2.4,-21.2 2.1,-21.2 0.3,-21.2 -0.05,-20.85 -1.1,-19.8 -2.15,-19.8 -2.35,-19.8 -2.5,-19.95 -2.65,-20.1 -2.65,-21.35 -2.65,-22.2 -1.9,-22.95 -1.3,-23.55 -1.3,-24.8 -1.3,-25.65 -1.05,-25.9 -0.85,-26.1 0.25,-26.1 1.45,-26.1 1.5,-26.05 1.7,-25.85 1.7,-25.1 1.7,-23 1.85,-22.85 2.05,-22.65 2.25,-22.65 2.3,-22.65 2.5,-22.45
NewNet21 on Top Layer "Top Layer-NewNet4" (solid, remove dead copper, pour order 1124): -1.15,-14.85 -1.15,-19.35 -1,-19.5 0.4,-20.9 1.3,-20.9 3.65,-20.9 6,-20.9 6.1,-20.8 6.25,-20.65 6.25,-19.8 6.25,-17.95 5.95,-17.65 5.9,-17.6 5.15,-17.6 2.8,-17.6 2.6,-17.4 2.55,-17.35 2.55,-17 2.55,-14.9 2.5,-14.85
NewNet21 on Top Layer "Top Layer-NewNet4" (solid, remove dead copper, pour order 1123): -23.1,-21.3 -23.1,-20.35 -23,-20.25 -22.85,-20.1 -22.45,-20.1 -21.65,-20.1 -21.35,-19.8 -21.1,-19.55 -21.1,-19.2 -21.1,-18.7 -20.95,-18.55 -20.9,-18.5 -19,-18.5 -18,-17.5 -17,-17.5 -10.95,-17.5 -10.75,-17.7 -10.75,-18.65 -10.75,-18.85 -10.1,-19.5 -10.05,-19.55 -8.4,-19.55 -8.3,-19.45 -8.1,-19.25 -8.1,-18.9 -8.1,-18 -7.9,-17.8 -7.85,-17.75 -6.35,-17.75 -5.25,-17.75 -5.15,-17.85 -5.1,-17.9 -5.1,-18.9 -5.1,-20.15 -5.85,-20.9 -6.05,-21.1 -9.1,-21.1 -11.55,-21.1 -12.15,-20.5 -12.4,-20.25 -12.4,-19.8 -12.4,-19.7 -12.9,-19.2 -15.8,-19.2 -16.65,-19.2 -17.65,-20.2 -18.8,-21.35 -20.55,-21.35 -23.05,-21.35 -23.1,-21.3
NewNet46 on Top Layer "Top Layer-NewNet4" (solid, remove dead copper, pour order 1120): -20.75,-29 -19.9,-29 -19.85,-29.05 -19.8,-29.1 -19.25,-29.1 -13.15,-29.1 -12.9,-29.35 -12.8,-29.45 -12.8,-30.2 -12.8,-30.65 -13.05,-30.9 -13.1,-30.95 -14.1,-30.95 -16.9,-30.95 -17.1,-31.15 -17.3,-31.15 -17.45,-31 -17.75,-30.7 -20.1,-30.7 -20.75,-30.7 -20.85,-30.6 -20.9,-30.55 -20.9,-30.25 -20.9,-29.1 -20.75,-28.95
NewNet54 on Top Layer "Top Layer-NewNet4" (solid, remove dead copper, pour order 1118): -20.75,-32.35 -18.25,-32.35 -18.1,-32.5 -17.9,-32.7 -17.9,-33.45 -17.9,-33.95 -18.05,-34.1 -18.15,-34.2 -19.8,-34.2 -20.55,-34.2 -20.75,-34 -20.8,-33.95 -20.8,-32.4 -20.75,-32.35
no net on Top Layer " " (hatched Horizontal grid 0.102 track 0.127, remove dead copper, pour order 1113): -81.934,-7.452
no net on Top Layer " " (hatched Horizontal grid 0.102 track 0.127, remove dead copper, pour order 1112): -88.307,-17.467
no net on Top Layer " " (hatched Horizontal grid 0.102 track 0.127, remove dead copper, pour order 1100): -82.207,-23.595
no net on Top Layer " " (hatched Horizontal grid 0.102 track 0.127, remove dead copper, pour order 1099): -81.407,-22.547
no net on Top Layer " " (hatched Horizontal grid 0.102 track 0.127, remove dead copper, pour order 1098): -82.507,-25.252
no net on Top Layer " " (hatched Horizontal grid 0.102 track 0.127, remove dead copper, pour order 1097): -60.907,-20.652
no net on Top Layer " " (hatched Horizontal grid 0.102 track 0.127, remove dead copper, pour order 1093): -60.554,-16.952
no net on Top Layer "   " (hatched Horizontal grid 0.102 track 0.127, remove dead copper, pour order 1082): -78.107,-33.752
no net on Top Layer "   " (hatched Horizontal grid 0.102 track 0.127, remove dead copper, pour order 1081): -78.907,-33.752
no net on Top Layer "   " (hatched Horizontal grid 0.102 track 0.127, remove dead copper, pour order 1080): -79.607,-33.752
no net on Top Layer "   " (hatched Horizontal grid 0.102 track 0.127, remove dead copper, pour order 1079): -79.907,-33.852
no net on Top Layer "   " (hatched Horizontal grid 0.102 track 0.127, remove dead copper, pour order 1078): -82.207,-22.547
no net on Top Layer "   " (hatched Horizontal grid 0.102 track 0.127, remove dead copper, pour order 1075): -64.507,-12.489
no net on Top Layer "   " (hatched Horizontal grid 0.102 track 0.127, remove dead copper, pour order 1074): -60.557,-16.752
no net on Top Layer "   " (hatched Horizontal grid 0.102 track 0.127, remove dead copper, pour order 1073): -64.507,-9.949
no net on Top Layer "    " (hatched Horizontal grid 0.102 track 0.127, remove dead copper, pour order 1070): -70.012,-12.752
no net on Top Layer "    " (hatched Horizontal grid 0.102 track 0.127, remove dead copper, pour order 1069): -58.507,-5.986
no net on Top Layer "    " (hatched Horizontal grid 0.102 track 0.127, remove dead copper, pour order 1068): -58.607,-5.885
no net on Top Layer "    " (hatched Horizontal grid 0.102 track 0.127, remove dead copper, pour order 1056): -44.007,-23.552
no net on Top Layer "    " (hatched Horizontal grid 0.102 track 0.127, remove dead copper, pour order 1055): -43.507,-29.252
no net on Top Layer "      " (hatched Horizontal grid 0.102 track 0.127, remove dead copper, pour order 1052): -44.907,0.048
no net on Top Layer "      " (hatched Horizontal grid 0.102 track 0.127, remove dead copper, pour order 1051): -57.207,-5.952
no net on Top Layer "     " (hatched Horizontal grid 0.102 track 0.127, remove dead copper, pour order 1050): -92.007,-14.952
no net on Top Layer "     " (hatched Horizontal grid 0.102 track 0.127, remove dead copper, pour order 1049): -92.007,-13.652
no net on Top Layer "     " (hatched Horizontal grid 0.102 track 0.127, remove dead copper, pour order 1048): -85.207,-13.852
no net on Top Layer "     " (hatched Horizontal grid 0.102 track 0.127, remove dead copper, pour order 1047): -68.507,-9.552
no net on Top Layer "     " (hatched Horizontal grid 0.102 track 0.127, remove dead copper, pour order 1046): -68.507,-10.552
no net on Top Layer "     " (hatched Horizontal grid 0.102 track 0.127, remove dead copper, pour order 1045): -66.007,0.048
no net on Top Layer "  " (hatched Horizontal grid 0.102 track 0.127, remove dead copper, pour order 1044): -72.107,-13.452
no net on Top Layer "  " (hatched Horizontal grid 0.102 track 0.127, remove dead copper, pour order 1043): -71.507,-5.952
no net on Top Layer "  " (hatched Horizontal grid 0.102 track 0.127, remove dead copper, pour order 1042): -92.007,-11.452
no net on Top Layer "  " (hatched Horizontal grid 0.102 track 0.127, remove dead copper, pour order 1041): -92.107,-11.752
no net on Top Layer "  " (hatched Horizontal grid 0.102 track 0.127, remove dead copper, pour order 1040): -92.107,-9.552
no net on Top Layer "  " (hatched Horizontal grid 0.102 track 0.127, remove dead copper, pour order 1039): -92.007,-12.452
no net on Top Layer "  " (hatched Horizontal grid 0.102 track 0.127, remove dead copper, pour order 1038): -88.007,-8.252
no net on Top Layer "  " (hatched Horizontal grid 0.102 track 0.127, remove dead copper, pour order 1037): -95.607,-10.852
no net on Top Layer "  " (hatched Horizontal grid 0.102 track 0.127, remove dead copper, pour order 1036): -95.607,-11.452
no net on Top Layer "  " (hatched Horizontal grid 0.102 track 0.127, remove dead copper, pour order 1035): -95.607,-10.852
no net on Top Layer "  " (hatched Horizontal grid 0.102 track 0.127, remove dead copper, pour order 1034): -95.607,-17.052
NewNet15 on Top Layer "Top Layer-NewNet4" (solid, remove dead copper, pour order 1119): 8.5,-30.5 8.5,-27.4 8.65,-27.25 8.7,-27.2 9.3,-27.2 10.35,-27.2 10.45,-27.3 10.45,-30.55 10.3,-30.7 10.25,-30.75 9.4,-30.75 8.7,-30.75 8.5,-30.55
NewNet15 on Top Layer "Top Layer-NewNet4" (solid, remove dead copper, pour order 1121): 11.3,-26.6 11.3,-24.7 11.05,-24.45 10.1,-23.5 8.6,-23.5 7.7,-23.5 7.55,-23.35 6.65,-22.45 5.9,-22.45 4.5,-22.45 3.5,-23.45 3.35,-23.6 3.35,-27.75 3.35,-29.3 3.6,-29.55 3.65,-29.5 4.05,-29.5 4.25,-29.3 4.25,-28.5 4.35,-28.4 4.35,-24.2 4.7,-23.85 4.85,-23.7 5.15,-23.7 6.8,-23.7 7,-23.9 7.15,-24.05 7.15,-24.8 7.15,-29.25 7.5,-29.6 7.55,-29.65 7.95,-29.65 8,-29.65 8.1,-29.55 8.2,-29.45 8.2,-29.1 8.2,-27.25 8.55,-26.9 8.65,-26.8 8.7,-26.8 11.1,-26.8 11.3,-26.6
